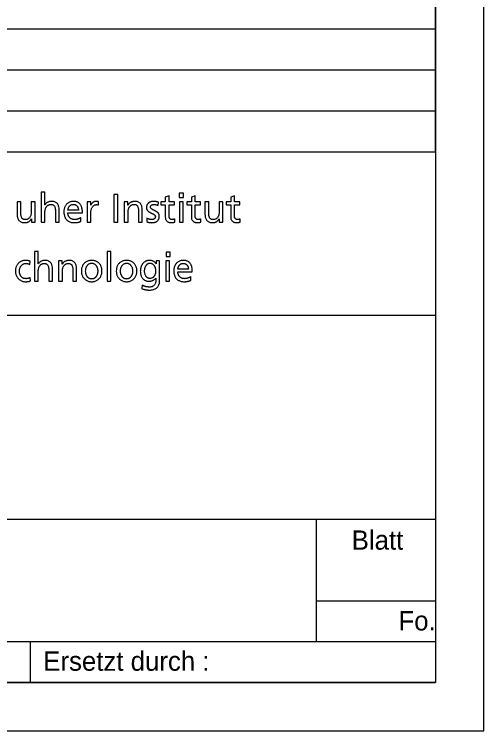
# Model space of a CAD drawing. Extents: x 0 to 420, y 0 to 297.
# Drawn here: x 396.16 to 420.5, y 0 to 37.12 of the extents above; entities that cross this region are included whole.
import ezdxf

# ---------------------------------------------------------------- set-up
doc = ezdxf.new("R2010")
doc.units = 0
doc.layers.add('90_Plankopf', color=7, linetype='Continuous')

msp = doc.modelspace()

# ---------------------------------------------------------------- linework, layer by layer
at = {"layer": '90_Plankopf'}
for p, q in [((418, 29.995), (418, 57.49)), ((329.06, 36.37), (418, 36.37)), ((329.06, 34.245), (418, 34.245)), ((329.06, 32.12), (418, 32.12)), ((329.06, 29.995), (418, 29.995)), ((329.06, 29.995), (418, 29.995)), ((418, 29.995), (418, 2.5)), ((418, 29.995), (418, 2.5)), ((400.528, 27.242), (400.528, 27.416)), ((403.616, 27.22), (403.633, 27.389)), ((399.486, 26.98), (398.941, 26.98)), ((398.941, 26.836), (399.693, 26.836)), ((399.612, 26.396), (399.612, 26.59)), ((403.036, 26.559), (403.026, 26.386)), ((404.481, 26.357), (404.481, 26.522)), ((405.833, 26.357), (405.833, 26.522)), ((407.872, 26.357), (407.872, 26.522)), ((396.976, 24.168), (396.992, 24.329)), ((405.186, 23.92), (404.642, 23.92)), ((404.642, 23.776), (405.393, 23.776)), ((397, 23.312), (396.986, 23.485)), ((405.312, 23.337), (405.312, 23.53)), ((402.798, 23.087), (402.777, 22.907)), ((376.001, 21.535), (418, 21.535)), ((376.001, 10.96), (418, 10.96)), ((411.824, 4.615), (411.824, 10.96)), ((411.824, 6.73), (418, 6.73)), ((376.001, 4.615), (418, 4.615)), ((397.001, 2.5), (397.001, 4.615)), ((418, 2.5), (329.06, 2.5)), ((334.9, 2.5), (418, 2.5)), ((334.9, 2.5), (418, 2.5))]:
    msp.add_line(p, q, dxfattribs=at)
for points in [[(0, 0), (420.5, 0), (420.5, 297), (0, 297)], [(12.5, 294.5), (418, 294.5), (418, 2.5), (12.5, 2.5)]]:
    msp.add_lwpolyline(points, close=True, dxfattribs=at)
for points in [[(397.755, 27.255), (397.751, 27.255), (397.751, 27.9), (397.557, 27.9), (397.557, 26.353), (397.751, 26.353), (397.751, 26.84)], [(404.927, 27.64), (404.927, 27.859), (404.708, 27.859), (404.708, 27.64), (404.927, 27.64)], [(401.323, 26.353), (401.529, 26.353), (401.529, 27.793), (401.323, 27.793), (401.323, 26.353)], [(404.186, 26.673), (404.186, 27.248), (404.464, 27.248), (404.464, 27.405), (404.186, 27.405), (404.186, 27.711), (403.992, 27.649), (403.992, 27.405), (403.754, 27.405), (403.754, 27.248), (403.992, 27.248), (403.992, 26.633)], [(405.538, 26.673), (405.538, 27.248), (405.816, 27.248), (405.816, 27.405), (405.538, 27.405), (405.538, 27.711), (405.344, 27.649), (405.344, 27.405), (405.106, 27.405), (405.106, 27.248), (405.344, 27.248), (405.344, 26.633)], [(407.577, 26.673), (407.577, 27.248), (407.855, 27.248), (407.855, 27.405), (407.577, 27.405), (407.577, 27.711), (407.383, 27.649), (407.383, 27.405), (407.146, 27.405), (407.146, 27.248), (407.383, 27.248), (407.383, 26.633)], [(396.502, 26.86), (396.502, 27.405), (396.308, 27.405), (396.308, 26.78)], [(397.047, 26.52), (397.051, 26.52), (397.051, 26.353), (397.239, 26.353), (397.239, 27.405), (397.045, 27.405), (397.045, 26.918)], [(400.126, 27.242), (400.122, 27.242), (400.122, 27.405), (399.94, 27.405), (399.94, 26.353), (400.134, 26.353), (400.134, 26.832)], [(402.058, 27.238), (402.054, 27.238), (402.054, 27.405), (401.866, 27.405), (401.866, 26.353), (402.06, 26.353), (402.06, 26.84)], [(404.72, 27.405), (404.72, 26.353), (404.914, 26.353), (404.914, 27.405), (404.72, 27.405)], [(406.242, 26.86), (406.242, 27.405), (406.048, 27.405), (406.048, 26.78)], [(406.786, 26.52), (406.79, 26.52), (406.79, 26.353), (406.978, 26.353), (406.978, 27.405), (406.784, 27.405), (406.784, 26.918)], [(398.293, 26.898), (398.293, 26.353), (398.487, 26.353), (398.487, 26.978)], [(402.603, 26.898), (402.603, 26.353), (402.797, 26.353), (402.797, 26.978)], [(397.409, 24.195), (397.405, 24.195), (397.405, 24.841), (397.211, 24.841), (397.211, 23.293), (397.405, 23.293), (397.405, 23.78)], [(400.982, 23.293), (401.176, 23.293), (401.176, 24.841), (400.982, 24.841), (400.982, 23.293)], [(404.247, 24.581), (404.247, 24.799), (404.028, 24.799), (404.028, 24.581), (404.247, 24.581)], [(398.652, 24.178), (398.647, 24.178), (398.647, 24.346), (398.46, 24.346), (398.46, 23.293), (398.654, 23.293), (398.654, 23.78)], [(403.698, 23.339), (403.698, 24.346), (403.518, 24.346), (403.518, 24.189), (403.514, 24.189)], [(404.015, 24.346), (404.015, 23.293), (404.209, 23.293), (404.209, 24.346), (404.015, 24.346)], [(397.948, 23.838), (397.948, 23.293), (398.142, 23.293), (398.142, 23.918)], [(399.196, 23.838), (399.196, 23.293), (399.39, 23.293), (399.39, 23.918)], [(403.5, 23.456), (403.504, 23.456), (403.504, 23.353)]]:
    msp.add_lwpolyline(points, dxfattribs=at)
for points in [[(397.751, 26.84), (397.751, 26.904), (397.757, 26.963), (397.77, 27.016), (397.782, 27.069), (397.802, 27.114), (397.828, 27.152), (397.854, 27.191), (397.887, 27.221), (397.927, 27.242), (397.968, 27.262), (398.015, 27.273), (398.071, 27.273), (398.127, 27.27), (398.171, 27.254), (398.204, 27.226), (398.236, 27.198), (398.259, 27.156), (398.273, 27.102), (398.287, 27.048), (398.294, 26.979), (398.293, 26.898)], [(398.487, 26.978), (398.488, 27.073), (398.474, 27.154), (398.446, 27.221), (398.418, 27.288), (398.374, 27.34), (398.316, 27.376), (398.258, 27.412), (398.184, 27.43), (398.093, 27.43), (398.019, 27.43), (397.954, 27.414), (397.895, 27.384), (397.837, 27.354), (397.791, 27.311), (397.755, 27.255)], [(399.693, 26.836), (399.693, 26.921), (399.685, 26.999), (399.67, 27.071), (399.654, 27.143), (399.628, 27.206), (399.592, 27.26), (399.556, 27.313), (399.509, 27.355), (399.449, 27.385), (399.389, 27.414), (399.316, 27.43), (399.228, 27.43), (399.154, 27.43), (399.086, 27.416), (399.026, 27.391), (398.966, 27.365), (398.914, 27.328), (398.87, 27.281), (398.827, 27.233), (398.794, 27.177), (398.771, 27.112), (398.747, 27.048), (398.736, 26.976), (398.735, 26.898), (398.735, 26.812), (398.746, 26.734), (398.768, 26.664), (398.789, 26.594), (398.823, 26.534), (398.868, 26.485), (398.912, 26.434), (398.969, 26.396), (399.037, 26.369), (399.106, 26.342), (399.187, 26.328), (399.28, 26.328), (399.337, 26.328), (399.386, 26.332), (399.427, 26.34), (399.467, 26.347), (399.502, 26.356), (399.532, 26.367), (399.561, 26.377), (399.588, 26.387), (399.612, 26.396)], [(398.941, 26.98), (398.945, 27.015), (398.953, 27.049), (398.965, 27.083), (398.977, 27.118), (398.994, 27.149), (399.017, 27.178), (399.04, 27.206), (399.068, 27.229), (399.102, 27.247), (399.136, 27.264), (399.177, 27.273), (399.224, 27.273), (399.266, 27.273), (399.303, 27.265), (399.336, 27.25), (399.368, 27.235), (399.395, 27.214), (399.418, 27.187), (399.44, 27.16), (399.457, 27.129), (399.469, 27.094), (399.48, 27.059), (399.486, 27.021), (399.486, 26.98)], [(400.528, 27.416), (400.515, 27.418), (400.502, 27.421), (400.49, 27.423), (400.478, 27.425), (400.464, 27.427), (400.45, 27.428), (400.436, 27.429), (400.419, 27.43), (400.401, 27.43), (400.363, 27.43), (400.327, 27.422), (400.291, 27.406), (400.256, 27.39), (400.224, 27.368), (400.196, 27.339), (400.167, 27.311), (400.144, 27.279), (400.126, 27.242)], [(400.134, 26.832), (400.135, 26.92), (400.147, 26.996), (400.17, 27.06), (400.194, 27.124), (400.227, 27.174), (400.27, 27.208), (400.312, 27.243), (400.363, 27.26), (400.421, 27.261), (400.438, 27.261), (400.456, 27.26), (400.474, 27.257), (400.493, 27.254), (400.511, 27.249), (400.528, 27.242)], [(402.797, 26.978), (402.797, 27.073), (402.783, 27.154), (402.755, 27.221), (402.727, 27.288), (402.684, 27.34), (402.626, 27.376), (402.568, 27.412), (402.493, 27.43), (402.402, 27.43), (402.353, 27.43), (402.306, 27.422), (402.261, 27.407), (402.216, 27.392), (402.176, 27.37), (402.14, 27.341), (402.105, 27.312), (402.077, 27.278), (402.058, 27.238)], [(402.06, 26.84), (402.06, 26.904), (402.066, 26.963), (402.079, 27.016), (402.092, 27.069), (402.111, 27.114), (402.137, 27.152), (402.163, 27.191), (402.196, 27.221), (402.237, 27.242), (402.277, 27.262), (402.325, 27.273), (402.38, 27.273), (402.436, 27.27), (402.48, 27.254), (402.513, 27.226), (402.546, 27.198), (402.569, 27.156), (402.582, 27.102), (402.597, 27.048), (402.603, 26.979), (402.603, 26.898)], [(403.633, 27.389), (403.595, 27.4), (403.556, 27.41), (403.517, 27.418), (403.478, 27.426), (403.436, 27.43), (403.391, 27.43), (403.339, 27.43), (403.29, 27.423), (403.245, 27.41), (403.2, 27.397), (403.161, 27.377), (403.127, 27.35), (403.094, 27.323), (403.067, 27.29), (403.049, 27.249), (403.03, 27.208), (403.02, 27.161), (403.02, 27.106), (403.02, 27.064), (403.029, 27.028), (403.045, 26.997), (403.061, 26.966), (403.083, 26.94), (403.11, 26.917), (403.137, 26.895), (403.167, 26.875), (403.199, 26.857), (403.232, 26.84), (403.264, 26.824), (403.296, 26.809), (403.329, 26.793), (403.358, 26.777), (403.385, 26.761), (403.412, 26.745), (403.434, 26.727), (403.451, 26.706), (403.467, 26.686), (403.475, 26.663), (403.476, 26.636), (403.475, 26.607), (403.469, 26.584), (403.457, 26.564), (403.445, 26.545), (403.43, 26.529), (403.41, 26.518), (403.39, 26.506), (403.369, 26.498), (403.346, 26.493), (403.323, 26.487), (403.3, 26.485), (403.278, 26.485), (403.258, 26.485), (403.235, 26.488), (403.207, 26.493), (403.179, 26.499), (403.15, 26.507), (403.12, 26.518), (403.09, 26.529), (403.062, 26.543), (403.036, 26.559)], [(403.026, 26.386), (403.071, 26.363), (403.117, 26.347), (403.167, 26.339), (403.215, 26.331), (403.265, 26.327), (403.315, 26.328), (403.362, 26.328), (403.408, 26.335), (403.451, 26.348), (403.495, 26.361), (403.534, 26.381), (403.569, 26.408), (403.603, 26.435), (403.631, 26.469), (403.651, 26.51), (403.671, 26.551), (403.682, 26.6), (403.682, 26.656), (403.682, 26.704), (403.673, 26.745), (403.657, 26.778), (403.64, 26.811), (403.619, 26.84), (403.592, 26.863), (403.565, 26.886), (403.535, 26.906), (403.503, 26.922), (403.47, 26.939), (403.438, 26.954), (403.406, 26.968), (403.373, 26.983), (403.343, 26.998), (403.317, 27.013), (403.289, 27.029), (403.268, 27.047), (403.251, 27.068), (403.235, 27.089), (403.226, 27.115), (403.226, 27.145), (403.226, 27.174), (403.235, 27.198), (403.252, 27.217), (403.269, 27.236), (403.292, 27.25), (403.32, 27.259), (403.347, 27.269), (403.378, 27.273), (403.412, 27.273), (403.423, 27.273), (403.439, 27.271), (403.457, 27.269), (403.475, 27.266), (403.494, 27.261), (403.515, 27.256), (403.535, 27.251), (403.554, 27.246), (403.572, 27.239), (403.59, 27.233), (403.605, 27.226), (403.616, 27.22)], [(396.308, 26.78), (396.308, 26.685), (396.322, 26.605), (396.35, 26.537), (396.378, 26.47), (396.421, 26.418), (396.479, 26.382), (396.537, 26.347), (396.612, 26.328), (396.702, 26.328), (396.751, 26.328), (396.799, 26.336), (396.844, 26.351), (396.889, 26.367), (396.929, 26.389), (396.964, 26.417), (397, 26.446), (397.027, 26.48), (397.047, 26.52)], [(397.045, 26.918), (397.045, 26.854), (397.039, 26.795), (397.026, 26.742), (397.013, 26.69), (396.994, 26.644), (396.968, 26.606), (396.941, 26.567), (396.908, 26.538), (396.868, 26.517), (396.828, 26.496), (396.78, 26.485), (396.725, 26.485), (396.669, 26.488), (396.624, 26.504), (396.592, 26.532), (396.559, 26.561), (396.536, 26.602), (396.522, 26.656), (396.508, 26.71), (396.502, 26.779), (396.502, 26.86)], [(399.612, 26.59), (399.6, 26.58), (399.583, 26.569), (399.559, 26.557), (399.536, 26.545), (399.51, 26.534), (399.48, 26.523), (399.45, 26.512), (399.419, 26.503), (399.386, 26.496), (399.353, 26.489), (399.32, 26.485), (399.288, 26.485), (399.242, 26.485), (399.198, 26.493), (399.156, 26.51), (399.115, 26.527), (399.078, 26.551), (399.046, 26.582), (399.014, 26.613), (398.988, 26.65), (398.97, 26.693), (398.951, 26.736), (398.942, 26.783), (398.941, 26.836)], [(406.048, 26.78), (406.048, 26.685), (406.061, 26.605), (406.089, 26.537), (406.117, 26.47), (406.16, 26.418), (406.219, 26.382), (406.277, 26.347), (406.351, 26.328), (406.442, 26.328), (406.491, 26.328), (406.538, 26.336), (406.583, 26.351), (406.628, 26.367), (406.669, 26.389), (406.704, 26.417), (406.739, 26.446), (406.767, 26.48), (406.786, 26.52)], [(406.784, 26.918), (406.784, 26.854), (406.778, 26.795), (406.765, 26.742), (406.753, 26.69), (406.733, 26.644), (406.707, 26.606), (406.681, 26.567), (406.648, 26.538), (406.607, 26.517), (406.567, 26.496), (406.519, 26.485), (406.464, 26.485), (406.408, 26.488), (406.364, 26.504), (406.331, 26.532), (406.299, 26.561), (406.276, 26.602), (406.262, 26.656), (406.248, 26.71), (406.241, 26.779), (406.242, 26.86)], [(403.992, 26.633), (403.992, 26.563), (404.005, 26.506), (404.031, 26.461), (404.057, 26.416), (404.095, 26.382), (404.143, 26.36), (404.191, 26.339), (404.249, 26.328), (404.316, 26.328), (404.347, 26.328), (404.377, 26.332), (404.405, 26.338), (404.434, 26.344), (404.459, 26.35), (404.481, 26.357)], [(404.481, 26.522), (404.466, 26.513), (404.448, 26.504), (404.426, 26.497), (404.404, 26.489), (404.379, 26.485), (404.349, 26.485), (404.319, 26.485), (404.292, 26.492), (404.267, 26.507), (404.243, 26.521), (404.223, 26.542), (404.208, 26.57), (404.194, 26.598), (404.186, 26.632), (404.186, 26.673)], [(405.344, 26.633), (405.344, 26.563), (405.357, 26.506), (405.383, 26.461), (405.409, 26.416), (405.447, 26.382), (405.495, 26.36), (405.543, 26.339), (405.601, 26.328), (405.668, 26.328), (405.699, 26.328), (405.729, 26.332), (405.757, 26.338), (405.786, 26.344), (405.811, 26.35), (405.833, 26.357)], [(405.833, 26.522), (405.818, 26.513), (405.8, 26.504), (405.778, 26.497), (405.756, 26.489), (405.731, 26.485), (405.701, 26.485), (405.671, 26.485), (405.644, 26.492), (405.619, 26.507), (405.595, 26.521), (405.575, 26.542), (405.56, 26.57), (405.546, 26.598), (405.538, 26.632), (405.538, 26.673)], [(407.383, 26.633), (407.383, 26.563), (407.396, 26.506), (407.422, 26.461), (407.449, 26.416), (407.486, 26.382), (407.534, 26.36), (407.582, 26.339), (407.64, 26.328), (407.707, 26.328), (407.738, 26.328), (407.768, 26.332), (407.796, 26.338), (407.825, 26.344), (407.85, 26.35), (407.872, 26.357)], [(407.872, 26.522), (407.857, 26.513), (407.839, 26.504), (407.818, 26.497), (407.796, 26.489), (407.77, 26.485), (407.74, 26.485), (407.71, 26.485), (407.683, 26.492), (407.658, 26.507), (407.634, 26.521), (407.614, 26.542), (407.6, 26.57), (407.585, 26.598), (407.577, 26.632), (407.577, 26.673)], [(396.992, 24.329), (396.973, 24.337), (396.951, 24.343), (396.924, 24.35), (396.897, 24.356), (396.869, 24.361), (396.84, 24.365), (396.811, 24.368), (396.783, 24.37), (396.757, 24.37), (396.676, 24.37), (396.603, 24.356), (396.537, 24.329), (396.472, 24.302), (396.415, 24.264), (396.368, 24.215), (396.321, 24.166), (396.284, 24.108), (396.259, 24.041), (396.234, 23.973), (396.221, 23.9), (396.22, 23.819), (396.221, 23.744), (396.234, 23.673), (396.26, 23.606), (396.285, 23.54), (396.322, 23.482), (396.37, 23.431), (396.417, 23.381), (396.474, 23.341), (396.539, 23.312), (396.605, 23.284), (396.677, 23.269), (396.757, 23.268), (396.781, 23.268), (396.806, 23.269), (396.833, 23.272), (396.861, 23.274), (396.889, 23.278), (396.917, 23.284), (396.946, 23.29), (396.973, 23.299), (397, 23.312)], [(396.986, 23.485), (396.966, 23.472), (396.944, 23.461), (396.92, 23.452), (396.896, 23.443), (396.872, 23.437), (396.848, 23.432), (396.823, 23.428), (396.8, 23.425), (396.777, 23.425), (396.728, 23.426), (396.684, 23.433), (396.645, 23.448), (396.607, 23.463), (396.574, 23.484), (396.546, 23.51), (396.518, 23.536), (396.496, 23.566), (396.478, 23.6), (396.461, 23.633), (396.448, 23.669), (396.439, 23.706), (396.431, 23.744), (396.427, 23.782), (396.427, 23.819), (396.427, 23.87), (396.434, 23.919), (396.449, 23.965), (396.464, 24.012), (396.486, 24.054), (396.515, 24.091), (396.544, 24.129), (396.579, 24.158), (396.621, 24.18), (396.663, 24.202), (396.711, 24.213), (396.765, 24.213), (396.797, 24.213), (396.83, 24.21), (396.866, 24.202), (396.902, 24.195), (396.938, 24.184), (396.976, 24.168)], [(397.405, 23.78), (397.405, 23.845), (397.411, 23.903), (397.424, 23.956), (397.437, 24.009), (397.456, 24.054), (397.482, 24.093), (397.508, 24.131), (397.542, 24.161), (397.582, 24.182), (397.622, 24.203), (397.67, 24.213), (397.725, 24.213), (397.781, 24.21), (397.825, 24.195), (397.858, 24.166), (397.891, 24.138), (397.914, 24.097), (397.928, 24.042), (397.942, 23.988), (397.948, 23.92), (397.948, 23.838)], [(398.142, 23.918), (398.142, 24.013), (398.128, 24.094), (398.1, 24.161), (398.072, 24.229), (398.029, 24.28), (397.971, 24.316), (397.913, 24.352), (397.838, 24.37), (397.748, 24.37), (397.674, 24.37), (397.608, 24.355), (397.55, 24.325), (397.492, 24.294), (397.445, 24.251), (397.409, 24.195)], [(399.39, 23.918), (399.391, 24.013), (399.377, 24.094), (399.349, 24.161), (399.321, 24.229), (399.277, 24.28), (399.219, 24.316), (399.161, 24.352), (399.087, 24.37), (398.996, 24.37), (398.947, 24.37), (398.9, 24.362), (398.855, 24.347), (398.81, 24.332), (398.769, 24.31), (398.734, 24.281), (398.699, 24.253), (398.671, 24.219), (398.652, 24.178)], [(398.654, 23.78), (398.654, 23.845), (398.66, 23.903), (398.673, 23.956), (398.685, 24.009), (398.705, 24.054), (398.731, 24.093), (398.757, 24.131), (398.79, 24.161), (398.83, 24.182), (398.871, 24.203), (398.918, 24.213), (398.974, 24.213), (399.03, 24.21), (399.074, 24.195), (399.107, 24.166), (399.139, 24.138), (399.162, 24.097), (399.176, 24.042), (399.19, 23.988), (399.197, 23.92), (399.196, 23.838)], [(400.697, 23.945), (400.691, 23.978), (400.682, 24.01), (400.671, 24.041), (400.645, 24.108), (400.609, 24.166), (400.562, 24.215), (400.515, 24.264), (400.458, 24.302), (400.393, 24.329), (400.328, 24.356), (400.255, 24.37), (400.175, 24.37), (400.094, 24.37), (400.021, 24.356), (399.955, 24.329), (399.889, 24.302), (399.833, 24.264), (399.786, 24.215), (399.739, 24.166), (399.702, 24.108), (399.677, 24.041), (399.651, 23.973), (399.639, 23.9), (399.638, 23.819)], [(399.844, 23.819), (399.844, 23.87), (399.852, 23.919), (399.867, 23.965), (399.882, 24.012), (399.903, 24.054), (399.932, 24.091), (399.96, 24.129), (399.994, 24.158), (400.035, 24.18), (400.076, 24.202), (400.122, 24.213), (400.175, 24.213), (400.226, 24.213), (400.272, 24.202), (400.313, 24.18), (400.353, 24.158), (400.388, 24.129), (400.416, 24.091), (400.444, 24.054), (400.466, 24.012), (400.48, 23.965), (400.495, 23.919), (400.503, 23.87), (400.503, 23.819), (400.503, 23.782), (400.499, 23.744), (400.49, 23.706), (400.482, 23.669), (400.47, 23.633), (400.452, 23.6), (400.436, 23.566), (400.414, 23.536), (400.388, 23.51), (400.362, 23.484), (400.332, 23.463), (400.296, 23.448), (400.261, 23.433), (400.22, 23.426), (400.175, 23.425), (400.129, 23.426), (400.088, 23.433), (400.052, 23.448), (400.017, 23.463), (399.986, 23.484), (399.959, 23.51), (399.933, 23.536), (399.912, 23.566), (399.895, 23.6), (399.878, 23.633), (399.865, 23.669), (399.857, 23.706), (399.849, 23.744), (399.844, 23.782), (399.844, 23.819)], [(402.507, 23.945), (402.501, 23.978), (402.492, 24.01), (402.481, 24.041), (402.455, 24.108), (402.419, 24.166), (402.372, 24.215), (402.325, 24.264), (402.268, 24.302), (402.203, 24.329), (402.138, 24.356), (402.065, 24.37), (401.985, 24.37), (401.904, 24.37), (401.831, 24.356), (401.765, 24.329), (401.699, 24.302), (401.643, 24.264), (401.596, 24.215), (401.549, 24.166), (401.512, 24.108), (401.487, 24.041), (401.461, 23.973), (401.449, 23.9), (401.448, 23.819)], [(401.655, 23.819), (401.655, 23.87), (401.662, 23.919), (401.677, 23.965), (401.692, 24.012), (401.713, 24.054), (401.742, 24.091), (401.77, 24.129), (401.805, 24.158), (401.845, 24.18), (401.886, 24.202), (401.932, 24.213), (401.985, 24.213), (402.036, 24.213), (402.082, 24.202), (402.123, 24.18), (402.163, 24.158), (402.198, 24.129), (402.226, 24.091), (402.254, 24.054), (402.276, 24.012), (402.29, 23.965), (402.305, 23.919), (402.313, 23.87), (402.313, 23.819), (402.313, 23.782), (402.309, 23.744), (402.3, 23.706), (402.292, 23.669), (402.28, 23.633), (402.263, 23.6), (402.246, 23.566), (402.224, 23.536), (402.198, 23.51), (402.172, 23.484), (402.142, 23.463), (402.106, 23.448), (402.071, 23.433), (402.03, 23.426), (401.985, 23.425), (401.939, 23.426), (401.898, 23.433), (401.862, 23.448), (401.827, 23.463), (401.796, 23.484), (401.769, 23.51), (401.743, 23.536), (401.722, 23.566), (401.705, 23.6), (401.688, 23.633), (401.675, 23.669), (401.667, 23.706), (401.659, 23.744), (401.655, 23.782), (401.655, 23.819)], [(403.514, 24.189), (403.495, 24.227), (403.47, 24.259), (403.44, 24.286), (403.409, 24.313), (403.371, 24.334), (403.327, 24.348), (403.282, 24.363), (403.229, 24.37), (403.167, 24.37), (403.104, 24.37), (403.047, 24.359), (402.996, 24.338), (402.946, 24.317), (402.902, 24.288), (402.864, 24.251), (402.827, 24.215), (402.796, 24.172), (402.771, 24.125), (402.746, 24.077), (402.727, 24.027), (402.715, 23.973), (402.703, 23.919), (402.697, 23.866), (402.697, 23.811), (402.697, 23.742), (402.706, 23.677), (402.725, 23.615), (402.743, 23.554), (402.772, 23.498), (402.809, 23.45), (402.846, 23.402), (402.893, 23.364), (402.949, 23.336), (403.006, 23.308), (403.071, 23.294), (403.147, 23.293), (403.192, 23.293), (403.236, 23.299), (403.279, 23.311), (403.323, 23.323), (403.363, 23.341), (403.401, 23.365), (403.439, 23.39), (403.472, 23.42), (403.5, 23.456)], [(403.196, 23.45), (403.151, 23.45), (403.11, 23.46), (403.074, 23.48), (403.038, 23.5), (403.007, 23.527), (402.982, 23.561), (402.956, 23.596), (402.937, 23.635), (402.923, 23.68), (402.91, 23.724), (402.903, 23.772), (402.903, 23.821), (402.903, 23.857), (402.907, 23.894), (402.915, 23.931), (402.922, 23.968), (402.934, 24.003), (402.95, 24.037), (402.965, 24.071), (402.985, 24.101), (403.008, 24.127), (403.032, 24.154), (403.059, 24.175), (403.091, 24.19), (403.122, 24.205), (403.157, 24.213), (403.196, 24.213), (403.248, 24.213), (403.293, 24.202), (403.331, 24.181), (403.37, 24.16), (403.402, 24.13), (403.427, 24.092), (403.453, 24.055), (403.472, 24.012), (403.485, 23.963), (403.497, 23.914), (403.504, 23.862), (403.504, 23.807), (403.504, 23.758), (403.496, 23.711), (403.481, 23.668), (403.466, 23.625), (403.445, 23.587), (403.418, 23.555), (403.391, 23.522), (403.359, 23.497), (403.321, 23.478), (403.283, 23.46), (403.242, 23.45), (403.196, 23.45)], [(405.393, 23.776), (405.393, 23.861), (405.385, 23.94), (405.37, 24.012), (405.354, 24.084), (405.328, 24.146), (405.292, 24.2), (405.256, 24.254), (405.209, 24.295), (405.149, 24.325), (405.089, 24.355), (405.016, 24.37), (404.928, 24.37), (404.854, 24.37), (404.786, 24.357), (404.726, 24.331), (404.666, 24.305), (404.614, 24.269), (404.57, 24.221), (404.527, 24.174), (404.494, 24.118), (404.471, 24.052), (404.447, 23.988), (404.436, 23.916), (404.435, 23.838), (404.435, 23.752), (404.446, 23.674), (404.468, 23.604), (404.49, 23.535), (404.523, 23.475), (404.568, 23.425), (404.612, 23.375), (404.669, 23.336), (404.737, 23.309), (404.806, 23.282), (404.887, 23.269), (404.98, 23.268), (405.037, 23.269), (405.086, 23.273), (405.127, 23.28), (405.167, 23.288), (405.202, 23.297), (405.232, 23.307), (405.261, 23.317), (405.288, 23.327), (405.312, 23.337)], [(404.642, 23.92), (404.645, 23.955), (404.653, 23.989), (404.665, 24.024), (404.677, 24.058), (404.695, 24.089), (404.717, 24.118), (404.74, 24.147), (404.768, 24.17), (404.802, 24.187), (404.836, 24.204), (404.877, 24.213), (404.924, 24.213), (404.966, 24.213), (405.003, 24.206), (405.036, 24.19), (405.068, 24.175), (405.096, 24.154), (405.118, 24.127), (405.14, 24.101), (405.157, 24.069), (405.169, 24.034), (405.18, 23.999), (405.186, 23.961), (405.186, 23.92)], [(399.638, 23.819), (399.639, 23.744), (399.652, 23.673), (399.677, 23.606), (399.703, 23.54), (399.74, 23.482), (399.787, 23.431), (399.835, 23.381), (399.891, 23.341), (399.957, 23.312), (400.022, 23.284), (400.095, 23.269), (400.175, 23.268), (400.254, 23.269), (400.326, 23.284), (400.391, 23.312), (400.457, 23.341), (400.513, 23.381), (400.56, 23.431), (400.608, 23.482), (400.644, 23.54), (400.67, 23.606), (400.696, 23.673), (400.709, 23.744), (400.709, 23.819), (400.709, 23.863), (400.705, 23.905), (400.697, 23.945)], [(401.448, 23.819), (401.449, 23.744), (401.462, 23.673), (401.487, 23.606), (401.513, 23.54), (401.55, 23.482), (401.597, 23.431), (401.645, 23.381), (401.701, 23.341), (401.767, 23.312), (401.832, 23.284), (401.905, 23.269), (401.985, 23.268), (402.064, 23.269), (402.136, 23.284), (402.201, 23.312), (402.267, 23.341), (402.323, 23.381), (402.37, 23.431), (402.418, 23.482), (402.454, 23.54), (402.48, 23.606), (402.506, 23.673), (402.519, 23.744), (402.519, 23.819), (402.519, 23.863), (402.515, 23.905), (402.507, 23.945)], [(405.312, 23.53), (405.3, 23.521), (405.283, 23.51), (405.26, 23.497), (405.237, 23.485), (405.21, 23.474), (405.18, 23.463), (405.151, 23.452), (405.119, 23.443), (405.086, 23.436), (405.053, 23.429), (405.021, 23.426), (404.988, 23.425), (404.942, 23.426), (404.898, 23.434), (404.857, 23.451), (404.815, 23.468), (404.778, 23.492), (404.746, 23.523), (404.714, 23.554), (404.688, 23.59), (404.67, 23.633), (404.652, 23.676), (404.642, 23.724), (404.642, 23.776)], [(402.777, 22.907), (402.833, 22.888), (402.883, 22.873), (402.926, 22.863), (402.968, 22.852), (403.008, 22.845), (403.045, 22.841), (403.082, 22.837), (403.118, 22.835), (403.155, 22.835), (403.28, 22.835), (403.383, 22.855), (403.463, 22.895), (403.544, 22.934), (403.603, 22.991), (403.641, 23.066), (403.679, 23.141), (403.698, 23.232), (403.698, 23.339)], [(403.504, 23.353), (403.503, 23.279), (403.491, 23.214), (403.465, 23.16), (403.439, 23.106), (403.402, 23.065), (403.353, 23.036), (403.304, 23.007), (403.246, 22.992), (403.178, 22.992), (403.142, 22.992), (403.11, 22.994), (403.079, 22.997), (403.049, 23), (403.019, 23.006), (402.99, 23.014), (402.961, 23.021), (402.931, 23.031), (402.9, 23.043), (402.869, 23.055), (402.835, 23.07), (402.798, 23.087)]]:
    msp.add_open_spline(points, degree=3, dxfattribs=at)

# ---------------------------------------------------------------- texts
for s, p in [('Blatt', (413.657, 9.379)), ('Fo.', (416.08, 5.196)), ('Ersetzt durch :', (397.663, 3.105))]:
    msp.add_text(s, height=1, dxfattribs=at).set_placement(p)

doc.saveas('drawing.dxf')
